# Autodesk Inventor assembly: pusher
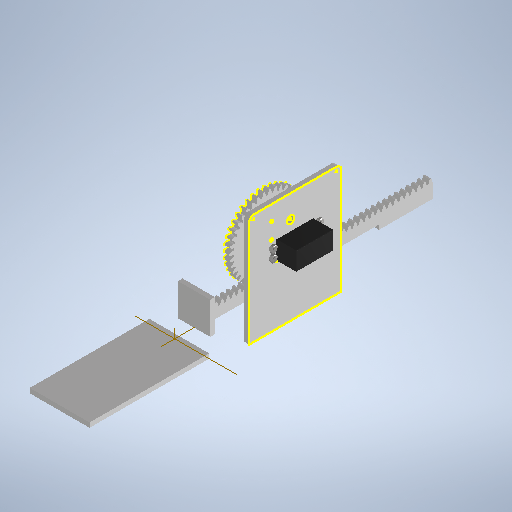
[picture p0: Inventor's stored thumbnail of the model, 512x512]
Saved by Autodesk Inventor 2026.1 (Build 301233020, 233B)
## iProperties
Created: 2026-10
Part Number: pusher
Document SubType Name: Assembly
Designer: alolo
Author: alolo
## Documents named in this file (9)
- C:\Users\hp\Documents\Inventor\DOM1_CartesianRobot\pusher.iam
- C:\Users\hp\Documents\Inventor\DOM1_CartesianRobot\pusher_pinion.ipt
- C:\Users\hp\Documents\Inventor\DOM1_CartesianRobot\Servo MG996R.ipt
- C:\Users\hp\Documents\Inventor\DOM1_CartesianRobot\pusher_rack.ipt
- C:\Users\hp\Documents\Inventor\DOM1_CartesianRobot\pusher_base.ipt
- C:\Users\hp\Documents\Inventor\DOM1_CartesianRobot\pusher_support.ipt
- C:\Users\hp\Documents\Inventor\DOM1_CartesianRobot\pusher_punch.ipt
- C:\Users\hp\Documents\Inventor\Content Center Files\R2026\en-US\ISO 4017(1)\ISO 4017 - M4 x 12 - ISO.ipt
- C:\Users\hp\Documents\Inventor\Content Center Files\R2026\en-US\ISO 4032(2)\ISO 4032 - M4 - ISO.ipt
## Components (14 placed, 8 different names)
1. Servo MG996R:1
2. pusher_base:1 — Mate:1, Mate:2, Mate:11, Slider:2, Flush:2, Mate:14
3. pusher_support
4. pusher_pinion:1 — Rotational:1, Rotation/Translation:1, Flush:1, Rotation/Translation:2
5. pusher_rack:1 — Slider:2, Rotation/Translation:1, Mate:12, Flush:1, Flush:3, Mate:31, Rotation/Translation:2
6. pusher_punch:2 — Mate:12, Mate:14, Flush:3, Mate:31
7. ISO 4017 M4 x 12:1 — Mate:15, Mate:16
8. ISO 4032 M4:1 — Mate:23, Mate:24
9. ISO 4017 M4 x 12:2 — Mate:17, Mate:18
10. ISO 4017 M4 x 12:3 — Mate:19, Mate:20
11. ISO 4017 M4 x 12:4 — Mate:21, Mate:22
12. ISO 4032 M4:2 — Mate:25, Mate:26
13. ISO 4032 M4:3 — Mate:27, Mate:28
14. ISO 4032 M4:4 — Mate:29, Mate:30
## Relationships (29: Mate 22, Flush 3, RelateRotateTranslate 2, RevoluteJoint 1, TranslationJoint 1)
- Mate:1: pusher_base:1
- Mate:2: pusher_base:1
- Rotational:1 [RevoluteJoint]: pusher_pinion:1
- Mate:11: pusher_base:1
- Slider:2 [TranslationJoint]: pusher_base:1 ↔ pusher_rack:1
- Rotation/Translation:1 [RelateRotateTranslate]: pusher_pinion:1 ↔ pusher_rack:1
- Mate:12: pusher_rack:1 ↔ pusher_punch:2
- Flush:1: pusher_pinion:1 ↔ pusher_rack:1
- Flush:2: pusher_base:1
- Mate:14: pusher_base:1 ↔ pusher_punch:2
- Mate:15: ISO 4017 M4 x 12:1
- Mate:16: ISO 4017 M4 x 12:1
- Mate:17: ISO 4017 M4 x 12:2
- Mate:18: ISO 4017 M4 x 12:2
- Mate:19: ISO 4017 M4 x 12:3
- Mate:20: ISO 4017 M4 x 12:3
- Mate:21: ISO 4017 M4 x 12:4
- Mate:22: ISO 4017 M4 x 12:4
- Mate:23: ISO 4032 M4:1
- Mate:24: ISO 4032 M4:1
- Mate:25: ISO 4032 M4:2
- Mate:26: ISO 4032 M4:2
- Mate:27: ISO 4032 M4:3
- Mate:28: ISO 4032 M4:3
- Mate:29: ISO 4032 M4:4
- Mate:30: ISO 4032 M4:4
- Flush:3: pusher_rack:1 ↔ pusher_punch:2
- Mate:31: pusher_rack:1 ↔ pusher_punch:2
- Rotation/Translation:2 [RelateRotateTranslate]: pusher_pinion:1 ↔ pusher_rack:1
